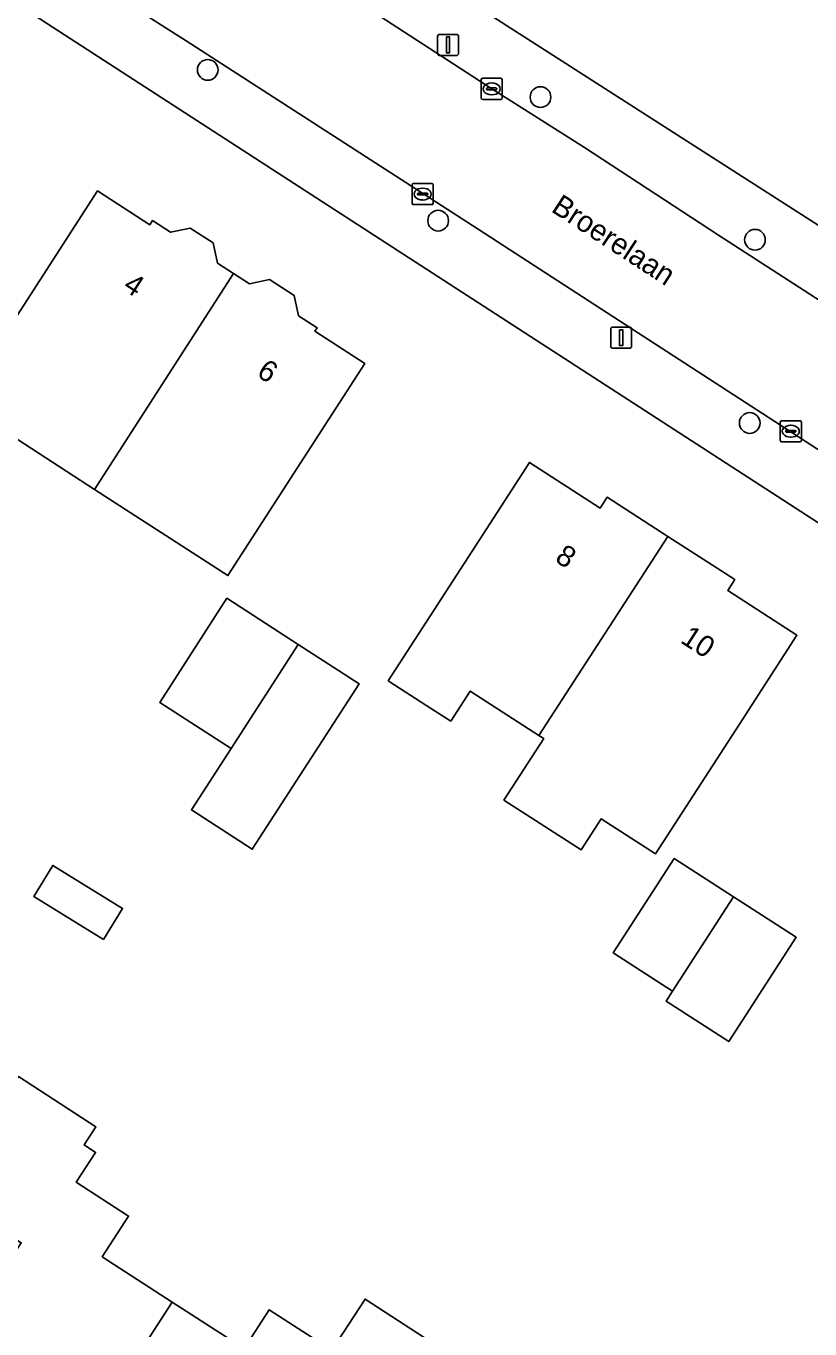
# Model space of a CAD drawing. Extents: x 161139 to 161601, y 381708 to 382245.
# Drawn here: x 161394.2 to 161431.3, y 382048.1 to 382109.7 of the extents above; entities that cross this region are included whole.
import ezdxf

# ---------------------------------------------------------------- set-up
doc = ezdxf.new("R2010")
doc.units = 0
for name, color, linetype in [('IMGEO_Boom', 7, 'Continuous'), ('IMGEO_Erf', 7, 'Continuous'), ('IMGEO_Kolk', 7, 'Continuous'), ('IMGEO_Lichtmast', 7, 'Continuous'), ('IMGEO_Openbare_ruimte_label', 7, 'Continuous'), ('IMGEO_Pand', 7, 'Continuous'), ('IMGEO_Pand_nummerreeks', 7, 'Continuous'), ('IMGEO_Rijbaan_lokaal_open', 7, 'Continuous'), ('IMGEO_Voetpad_open', 7, 'Continuous')]:
    doc.layers.add(name, color=color, linetype=linetype)

msp = doc.modelspace()

# ---------------------------------------------------------------- linework, layer by layer
at = {"layer": 'IMGEO_Boom'}
for centre in [(161402.785, 382107.638), (161418.516, 382106.351), (161413.679, 382100.51), (161428.654, 382099.608), (161428.405, 382090.947)]:
    msp.add_circle(centre, 0.489, dxfattribs=at)
at = {"layer": 'IMGEO_Erf'}
for points in [[(161553.295, 382144.911), (161544.61, 382147.101), (161500, 382158.072), (161477.956, 382163.494), (161457.897, 382168.303), (161418.52, 382178.097), (161389.844, 382185.251), (161387.058, 382185.651), (161384.186, 382184.996), (161381.949, 382183.375), (161380.259, 382181.034), (161377.586, 382172.934), (161374.321, 382163.969), (161372.26, 382158.835), (161369.98, 382153.637), (161365.084, 382143.565), (161365.175, 382143.293), (161389.855, 382127.317), (161408.789, 382114.947), (161450.498, 382088.211), (161500, 382056.07), (161523.437, 382040.853), (161561.628, 382099.383), (161581.409, 382129.761)], [(161320.525, 382089.631), (161313.623, 382083.997), (161443.483, 382000), (161462.38, 381987.777), (161470.3, 382000), (161498.24, 382043.117), (161359.011, 382133.266)], [(161393.835, 382060.054), (161397.496, 382057.684), (161396.939, 382056.824), (161397.487, 382056.47), (161396.573, 382055.059), (161399.046, 382053.458), (161397.803, 382051.538), (161401.11, 382049.396), (161404.506, 382047.197), (161405.696, 382049.035), (161408.654, 382047.119), (161410.222, 382049.541), (161413.97, 382047.113)]]:
    msp.add_lwpolyline(points, dxfattribs=at)
for points in [[(161403.739, 382083.736), (161397.438, 382087.809), (161391.146, 382091.877), (161391.97, 382093.238), (161394.864, 382097.714), (161397.578, 382101.913), (161400.051, 382100.314), (161400.18, 382100.512), (161401.027, 382099.965), (161401.953, 382100.163), (161403.047, 382099.456), (161403.251, 382098.506), (161404.008, 382098.017), (161404.764, 382097.529), (161405.713, 382097.732), (161406.876, 382096.98), (161407.084, 382096.013), (161407.959, 382095.447), (161407.856, 382095.287), (161410.219, 382093.759), (161407.505, 382089.561)], [(161415.195, 382078.275), (161414.276, 382076.854), (161413.146, 382077.584), (161411.323, 382078.762), (161415.281, 382084.884), (161417.995, 382089.083), (161421.331, 382086.926), (161421.664, 382087.44), (161424.527, 382085.589), (161427.694, 382083.542), (161427.363, 382083.03), (161430.637, 382080.913), (161427.923, 382076.715), (161423.959, 382070.583), (161421.387, 382072.245), (161420.433, 382070.768), (161416.79, 382073.123), (161418.669, 382076.029), (161418.44, 382076.177)], [(161402.012, 382072.66), (161403.888, 382075.567), (161400.518, 382077.743), (161403.691, 382082.661), (161407.065, 382080.481), (161409.941, 382078.622), (161404.89, 382070.801)], [(161424.837, 382070.37), (161427.641, 382068.557), (161430.604, 382066.641), (161427.412, 382061.705), (161424.449, 382063.621), (161424.754, 382064.093), (161421.951, 382065.904)], [(161397.864, 382066.54), (161394.564, 382068.571), (161395.465, 382070.035), (161398.765, 382068.004)]]:
    msp.add_lwpolyline(points, close=True, dxfattribs=at)
at = {"layer": 'IMGEO_Kolk'}
for p, q in [((161415.709, 382106.313), (161415.709, 382107.165)), ((161415.784, 382107.239), (161416.636, 382107.239)), ((161416.71, 382107.165), (161416.71, 382106.313)), ((161415.968, 382106.733), (161415.968, 382106.745)), ((161416.406, 382106.696), (161416.008, 382106.696)), ((161416.011, 382106.782), (161416.409, 382106.782)), ((161416.197, 382107.019), (161416.222, 382107.019)), ((161416.452, 382106.745), (161416.452, 382106.733)), ((161416.636, 382106.239), (161415.784, 382106.239)), ((161416.22, 382106.459), (161416.195, 382106.459)), ((161412.445, 382101.341), (161412.445, 382102.193)), ((161412.52, 382102.267), (161413.372, 382102.267)), ((161413.446, 382102.193), (161413.446, 382101.341)), ((161412.704, 382101.761), (161412.704, 382101.773)), ((161413.142, 382101.724), (161412.744, 382101.724)), ((161412.747, 382101.81), (161413.145, 382101.81)), ((161412.933, 382102.047), (161412.958, 382102.047)), ((161413.188, 382101.773), (161413.188, 382101.761)), ((161413.372, 382101.267), (161412.52, 382101.267)), ((161412.956, 382101.487), (161412.931, 382101.487)), ((161429.846, 382090.131), (161429.846, 382090.983)), ((161429.921, 382091.057), (161430.773, 382091.057)), ((161430.105, 382090.551), (161430.105, 382090.563)), ((161430.543, 382090.514), (161430.145, 382090.514)), ((161430.148, 382090.6), (161430.546, 382090.6)), ((161430.334, 382090.837), (161430.359, 382090.837)), ((161430.589, 382090.563), (161430.589, 382090.551)), ((161430.847, 382090.983), (161430.847, 382090.131)), ((161430.773, 382090.057), (161429.921, 382090.057)), ((161430.357, 382090.277), (161430.332, 382090.277))]:
    msp.add_line(p, q, dxfattribs=at)
for points in [[(161415.709, 382106.313), (161415.709, 382107.165)], [(161415.784, 382107.239), (161416.636, 382107.239)], [(161416.71, 382107.165), (161416.71, 382106.313)], [(161416.636, 382106.239), (161415.784, 382106.239)], [(161412.445, 382101.341), (161412.445, 382102.193)], [(161412.52, 382102.267), (161413.372, 382102.267)], [(161413.446, 382102.193), (161413.446, 382101.341)], [(161413.372, 382101.267), (161412.52, 382101.267)], [(161429.846, 382090.131), (161429.846, 382090.983)], [(161429.921, 382091.057), (161430.773, 382091.057)], [(161430.847, 382090.983), (161430.847, 382090.131)], [(161430.773, 382090.057), (161429.921, 382090.057)]]:
    msp.add_lwpolyline(points, dxfattribs=at)
for centre, radius, start, end in [((161415.786, 382107.163), 0.0765, 91.55205, 178.44795), ((161415.786, 382107.163), 0.0765, 91.55205, 178.44795), ((161416.634, 382107.163), 0.0765, 1.55205, 88.44795), ((161416.634, 382107.163), 0.0765, 1.55205, 88.44795), ((161416.008, 382106.742), 0.0403, 85.87752, 175.75265), ((161416.005, 382106.732), 0.0366, 178.93798, 274.71019), ((161416.409, 382106.739), 0.043, 264.86636, 352.45326), ((161416.413, 382106.744), 0.0386, 1.73085, 96.63898), ((161415.786, 382106.315), 0.0765, 181.55205, 268.44795), ((161415.786, 382106.315), 0.0765, 181.55205, 268.44795), ((161416.634, 382106.315), 0.0765, 271.55205, 358.44795), ((161416.634, 382106.315), 0.0765, 271.55205, 358.44795), ((161412.522, 382102.191), 0.0765, 91.55205, 178.44795), ((161412.522, 382102.191), 0.0765, 91.55205, 178.44795), ((161413.37, 382102.191), 0.0765, 1.55205, 88.44795), ((161413.37, 382102.191), 0.0765, 1.55205, 88.44795), ((161412.744, 382101.77), 0.0403, 85.87752, 175.75265), ((161412.741, 382101.76), 0.0366, 178.93798, 274.71019), ((161413.145, 382101.767), 0.043, 264.86636, 352.45326), ((161413.149, 382101.772), 0.0386, 1.73085, 96.63898), ((161412.522, 382101.343), 0.0765, 181.55205, 268.44795), ((161412.522, 382101.343), 0.0765, 181.55205, 268.44795), ((161413.37, 382101.343), 0.0765, 271.55205, 358.44795), ((161413.37, 382101.343), 0.0765, 271.55205, 358.44795), ((161429.923, 382090.981), 0.0765, 91.55205, 178.44795), ((161429.923, 382090.981), 0.0765, 91.55205, 178.44795), ((161430.145, 382090.56), 0.0403, 85.87752, 175.75265), ((161430.142, 382090.55), 0.0366, 178.93798, 274.71019), ((161430.546, 382090.557), 0.043, 264.86636, 352.45326), ((161430.55, 382090.562), 0.0386, 1.73085, 96.63898), ((161430.771, 382090.981), 0.0765, 1.55205, 88.44795), ((161430.771, 382090.981), 0.0765, 1.55205, 88.44795), ((161429.923, 382090.133), 0.0765, 181.55205, 268.44795), ((161429.923, 382090.133), 0.0765, 181.55205, 268.44795), ((161430.771, 382090.133), 0.0765, 271.55205, 358.44795), ((161430.771, 382090.133), 0.0765, 271.55205, 358.44795)]:
    msp.add_arc(centre, radius, start, end, dxfattribs=at)
for centre, major_axis, ratio, start_param, end_param in [((161416.196, 382106.739), (-0.387, 0.002), 0.722429, 4.712389, 7.853982), ((161416.221, 382106.739), (-0.39, 0.002), 0.717154, 1.570796, 4.712389), ((161412.932, 382101.767), (-0.387, 0.002), 0.722429, 4.712389, 7.853982), ((161412.957, 382101.767), (-0.39, 0.002), 0.717154, 1.570796, 4.712389), ((161430.333, 382090.557), (-0.387, 0.002), 0.722429, 4.712389, 7.853982), ((161430.358, 382090.557), (-0.39, 0.002), 0.717154, 1.570796, 4.712389)]:
    msp.add_ellipse(centre, major_axis=major_axis, ratio=ratio, start_param=start_param, end_param=end_param, dxfattribs=at)
at = {"layer": 'IMGEO_Lichtmast'}
for p, q in [((161413.65, 382108.417), (161413.65, 382109.217)), ((161413.65, 382109.217), (161413.65, 382108.417)), ((161413.75, 382109.317), (161414.54, 382109.317)), ((161414.54, 382109.317), (161413.75, 382109.317)), ((161414.64, 382109.217), (161414.64, 382108.417)), ((161414.64, 382108.417), (161414.64, 382109.217)), ((161414.54, 382108.317), (161413.75, 382108.317)), ((161413.75, 382108.317), (161414.54, 382108.317)), ((161421.933, 382095.482), (161422.723, 382095.482)), ((161422.723, 382095.482), (161421.933, 382095.482)), ((161421.833, 382094.582), (161421.833, 382095.382)), ((161421.833, 382095.382), (161421.833, 382094.582)), ((161422.823, 382095.382), (161422.823, 382094.582)), ((161422.823, 382094.582), (161422.823, 382095.382)), ((161422.723, 382094.482), (161421.933, 382094.482)), ((161421.933, 382094.482), (161422.723, 382094.482))]:
    msp.add_line(p, q, dxfattribs=at)
for points in [[(161414.07, 382109.192), (161414.22, 382109.192), (161414.22, 382108.442), (161414.07, 382108.442), (161414.07, 382109.192)], [(161422.253, 382095.357), (161422.403, 382095.357), (161422.403, 382094.607), (161422.253, 382094.607), (161422.253, 382095.357)]]:
    msp.add_lwpolyline(points, dxfattribs=at)
for centre, start, end in [((161413.75, 382109.217), 90, 180), ((161413.75, 382109.217), 90, 180), ((161414.54, 382109.217), 0, 90), ((161414.54, 382109.217), 360, 90), ((161413.75, 382108.417), 180, 270), ((161413.75, 382108.417), 180, 270), ((161414.54, 382108.417), 270, 0), ((161414.54, 382108.417), 270, 0), ((161421.933, 382095.382), 90, 180), ((161421.933, 382095.382), 90, 180), ((161422.723, 382095.382), 0, 90), ((161422.723, 382095.382), 360, 90), ((161421.933, 382094.582), 180, 270), ((161421.933, 382094.582), 180, 270), ((161422.723, 382094.582), 270, 0), ((161422.723, 382094.582), 270, 0)]:
    msp.add_arc(centre, 0.1, start, end, dxfattribs=at)
at = {"layer": 'IMGEO_Pand'}
for points in [[(161397.438, 382087.809), (161404.008, 382098.017), (161403.251, 382098.506), (161403.047, 382099.456), (161401.953, 382100.163), (161401.027, 382099.965), (161400.18, 382100.512), (161400.051, 382100.314), (161397.578, 382101.913), (161394.864, 382097.714), (161391.97, 382093.238), (161391.146, 382091.877)], [(161397.438, 382087.809), (161403.739, 382083.736), (161407.505, 382089.561), (161410.219, 382093.759), (161407.856, 382095.287), (161407.959, 382095.447), (161407.084, 382096.013), (161406.876, 382096.98), (161405.713, 382097.732), (161404.764, 382097.529), (161404.008, 382098.017)], [(161424.527, 382085.589), (161421.664, 382087.44), (161421.331, 382086.926), (161417.995, 382089.083), (161415.281, 382084.884), (161411.323, 382078.762), (161413.146, 382077.584), (161414.276, 382076.854), (161415.195, 382078.275), (161418.44, 382076.177)], [(161430.637, 382080.913), (161427.363, 382083.03), (161427.694, 382083.542), (161424.527, 382085.589), (161418.44, 382076.177), (161418.669, 382076.029), (161416.79, 382073.123), (161420.433, 382070.768), (161421.387, 382072.245), (161423.959, 382070.583), (161427.923, 382076.715)], [(161407.065, 382080.481), (161403.691, 382082.661), (161400.518, 382077.743), (161403.888, 382075.567)], [(161409.941, 382078.622), (161407.065, 382080.481), (161403.888, 382075.567), (161402.012, 382072.66), (161404.89, 382070.801)], [(161424.754, 382064.093), (161427.641, 382068.557), (161424.837, 382070.37), (161421.951, 382065.904)], [(161397.864, 382066.54), (161398.765, 382068.004), (161395.465, 382070.035), (161394.564, 382068.571)], [(161424.754, 382064.093), (161424.449, 382063.621), (161427.412, 382061.705), (161430.604, 382066.641), (161427.641, 382068.557)], [(161393.772, 382038.063), (161401.11, 382049.396), (161397.803, 382051.538), (161399.046, 382053.458), (161396.573, 382055.059), (161397.487, 382056.47), (161396.939, 382056.824), (161397.496, 382057.684), (161393.835, 382060.054), (161390.289, 382054.594), (161393.97, 382052.203), (161387.46, 382042.15)], [(161401.11, 382049.396), (161393.772, 382038.063), (161400.087, 382033.974), (161406.584, 382044.008), (161410.358, 382041.557), (161413.97, 382047.113), (161410.222, 382049.541), (161408.654, 382047.119), (161405.696, 382049.035), (161404.506, 382047.197)]]:
    msp.add_lwpolyline(points, close=True, dxfattribs=at)
at = {"layer": 'IMGEO_Rijbaan_lokaal_open'}
for points in [[(161521.765, 382038.348), (161512.078, 382044.654), (161498.469, 382053.534), (161494.669, 382055.998), (161485.554, 382061.86), (161483.251, 382063.426), (161480.028, 382065.466), (161471.488, 382070.983), (161468.287, 382073.003), (161467.324, 382073.702), (161460.192, 382078.284), (161453.24, 382082.778), (161444.055, 382088.754), (161440.905, 382090.804), (161426.931, 382099.82), (161420.597, 382103.968), (161416.21, 382106.739), (161403.197, 382115.21)], [(161398.574, 382111.058), (161401.761, 382109.008), (161415.306, 382100.289), (161421.669, 382096.147), (161435.549, 382087.163), (161442.527, 382082.644), (161453.542, 382075.54), (161460.477, 382071.037), (161473.195, 382062.836), (161477.592, 382059.945), (161498.051, 382046.741), (161499.796, 382045.589), (161510.796, 382038.454), (161522.385, 382030.943)]]:
    msp.add_lwpolyline(points, dxfattribs=at)
at = {"layer": 'IMGEO_Voetpad_open'}
for points in [[(161421.669, 382096.147), (161415.306, 382100.289), (161401.761, 382109.008), (161398.574, 382111.058), (161389.569, 382116.981), (161386.277, 382119.018), (161382.915, 382121.211), (161379.746, 382123.279), (161360.833, 382135.554), (161359.011, 382133.266), (161498.24, 382043.117), (161500.799, 382041.385)], [(161403.197, 382115.21), (161416.21, 382106.739), (161420.597, 382103.968), (161426.931, 382099.82), (161440.905, 382090.804), (161444.055, 382088.754), (161453.24, 382082.778), (161460.192, 382078.284), (161467.324, 382073.702), (161468.287, 382073.003), (161471.488, 382070.983), (161480.028, 382065.466), (161483.251, 382063.426), (161485.554, 382061.86), (161494.669, 382055.998), (161498.469, 382053.534), (161512.078, 382044.654), (161521.765, 382038.348), (161525.596, 382035.854), (161527.949, 382034.358)], [(161450.498, 382088.211), (161408.789, 382114.947)], [(161499.883, 382045.525), (161499.84, 382045.557), (161499.796, 382045.589), (161498.051, 382046.741), (161477.592, 382059.945), (161473.195, 382062.836), (161460.477, 382071.037), (161453.542, 382075.54), (161442.527, 382082.644), (161435.549, 382087.163), (161421.669, 382096.147)]]:
    msp.add_lwpolyline(points, dxfattribs=at)

# ---------------------------------------------------------------- texts
at = {"layer": 'IMGEO_Openbare_ruimte_label'}
msp.add_text('Broerelaan', height=1, rotation=326.91369, dxfattribs=at).set_placement((161418.973, 382100.972))
at = {"layer": 'IMGEO_Pand_nummerreeks'}
for s, rotation, p in [('4', 327.17621, (161398.728, 382097.268)), ('6', 327.17621, (161405.049, 382093.191)), ('8', 327.12941, (161419.148, 382084.434)), ('10', 327.12941, (161425.081, 382080.597))]:
    msp.add_text(s, height=1, rotation=rotation, dxfattribs=at).set_placement(p)

doc.saveas('drawing.dxf')
